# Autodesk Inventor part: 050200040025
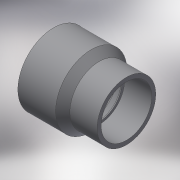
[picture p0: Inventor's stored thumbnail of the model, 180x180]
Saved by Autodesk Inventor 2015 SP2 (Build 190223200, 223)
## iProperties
Created: 2017-10
Part Number: 050200040025
Material: Generic
Description: PLASSON REDUCING SOCKET M.F.40(32)25 CEMENTED
Document SubType Name: Modeling
Designer: KIM
Density: 1 g/cm^3
Appearance: Default
Author: KIM
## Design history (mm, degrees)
derived "050200.ipt"
feature "Solid1::050200.ipt"
tag "TaggingFeature1"
body "Solid1"
other parameters: "d0" = 49, "d1" = 26, "d2" = 19, "d3" = 24, "d4" = 25, "d5" = 32, "d6" = 32, "d8" = 22.5, "d9" = 45 deg, "d12" = 0.32, "d_" = 32, "d_1" = 25, "L_" = 26, "l_" = 24, "l_1" = 19, "E_" = 32, "H_" = 49, "d11" = 45 deg
